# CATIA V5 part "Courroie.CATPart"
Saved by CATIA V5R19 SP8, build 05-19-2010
Part number: Courroie
Nomenclature: 58
Material "Caoutchouc": density 910 kg/m3, Young's modulus 2e+06 Pa, Poisson ratio 0.49, thermal expansion 0.000162 1/K
Bounding box of the stored display mesh (mm): x 4.57 to 18.61, y -15.72 to 178.98, z -41.51 to 41.51
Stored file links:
  C:\Users\rphgr\Desktop\0_Tapis_TC520B_vitesse\Courroie.CATPart
  D:\Documents\1_Travail\1 - ac-limoges.fr\ac-limoges.fr\Emmanuel Maynard - STI2D_Turgot\3 - Supports\Tapis de course TC520B\Tapis de course TC520B_Ca\0_Tapis_TC520B.CATProduct
  D:\Documents\1_Travail\1 - ac-limoges.fr\ac-limoges.fr\Emmanuel Maynard - STI2D_Turgot\3 - Supports\Tapis de course TC520B\Tapis de course TC520B_Ca\Poulie_inertie.CATPart
  C:\Users\rphgr\Desktop\0_Tapis_TC520B_vitesse\Tambour_moteur.CATPart
  D:\Documents\1_Travail\1 - ac-limoges.fr\ac-limoges.fr\Emmanuel Maynard - STI2D_Turgot\3 - Supports\Tapis de course TC520B\Tapis de course TC520B_Ca\Cadre Plateau.CATPart
  D:\Programmes\DassaultSysteme\win_b64\startup\materials\French\Catalog.CATMaterial
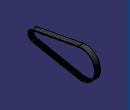
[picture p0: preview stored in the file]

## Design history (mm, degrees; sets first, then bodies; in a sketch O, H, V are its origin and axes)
AxisSystem1: origin (0, 0, 0), X (1, 0, 0), Y (0, 1, 0), Z (0, 0, 1)
Set1
  DatumCurve1: linked copy from another document
Set2
  DatumCurve2
  DatumPoint1
  DatumPoint2
Body1 (main body)
  Sketch1 on YZ plane of AxisSystem1, origin (0, 0, 0), H (0, 1, 0), V (0, 0, 1)
    arc A1 centre (0, 0) radius 14.21 from (-2.6656, 13.9577) to (-2.6656, -13.9577) ccw
    arc A2 centre (137.4818, 0) radius 40 from (129.9783, -39.2899) to (129.9783, 39.2899) ccw
    point P1 (137.4818, 0)
    line L1 (-2.6656, 13.9577) -> (129.9783, 39.2899)
    line L2 (129.9783, -39.2899) -> (-2.6656, -13.9577)
    reference projected circle E1 centre (0, 0) radius 14.21 from edge of DatumCurve2
    reference projected circle E2 centre (137.4818, 0) radius 40 from edge of DatumCurve1
    tangency: L1 A2, L2 A1, L1 A1, L2 A2
    coincidence: E1 A1, P1 H, A2 E2
  Plane1: type Normal, Curve Sketch1, RefPoint vertex [element of Sketch1 | element of Sketch1]
  Sketch2 on Plane1, origin (0, 0, 0), H (0, -0.1876, 0.9822), V (1, 0, 0)
    line L1 (14.1542, 6.8164) -> (12.48, 6.207)
    line L2 (12.48, 5.2737) -> (14.1542, 4.6643)
    arc A1 centre (14.12, 4.5703) radius 0.1 from (14.1542, 4.6643) to (14.22, 4.5703) cw
    point P2 (14.12, 4.5703)
    arc A2 centre (14.12, 6.9103) radius 0.1 from (14.1542, 6.8164) to (14.22, 6.9103) ccw
    point P4 (14.12, 6.9103)
    line L3 (14.22, 6.9103) -> (15.72, 6.9103)
    line L4 (15.72, 6.9103) -> (15.72, 4.5703)
    line L5 (15.72, 4.5703) -> (14.22, 4.5703)
    line L6 (12.48, 6.207) -> (12.48, 5.2737)
    reference projected point E1 (0, 9.816) from vertex of DatumPoint1
    reference projected point E2 (0, 1.6647) from vertex of DatumPoint2
    radius A1 = 0.1
    radius A2 = 0.1
    distance L3 L5 = 2.34
    angle L1 L2 = 40
    distance L6 L4 = 3.24
    angle L4 L1 = 70
    length L3 = 1.5
    length L5 = 1.5 {= Sketch2.length(L3)}
    tangency: A1 L2, A2 L1
    horizontal: L3 H, L5 H
    vertical: L4 V
    coincidence: P4 L3, P2 L5, L2 E1, L1 E2
  Rib1: profile Sketch2, centre curve Sketch1
  RectPattern1: of the body so far, direction 1 instances 6, spacing 2.34, along edge [XY plane of AxisSystem1 | ZX plane of AxisSystem1]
